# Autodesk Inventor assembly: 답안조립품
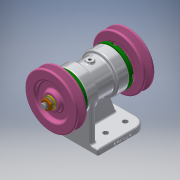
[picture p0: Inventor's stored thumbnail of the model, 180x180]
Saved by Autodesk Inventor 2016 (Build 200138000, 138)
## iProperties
Created: 2020-06
Part Number: 답안조립품
Material: 일반
Document SubType Name: Assembly
Designer: user
Author: user
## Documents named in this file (12)
- C:\Users\user\Desktop\700606V1056\답안조립품.iam
- C:\Users\user\Desktop\700606V1056\본체.ipt
- C:\Users\user\Desktop\700606V1056\베어링 6204.ipt
- C:\Users\user\Desktop\700606V1056\축.ipt
- C:\Users\user\Desktop\700606V1056\커버.ipt
- C:\Users\user\Desktop\700606V1056\오일 실 20 32 5.ipt
- C:\Users\user\Desktop\700606V1056\키 5x5x12.ipt
- C:\Users\user\Desktop\700606V1056\V-벨트풀리.ipt
- C:\Users\user\Desktop\700606V1056\평면 와셔 10x21.ipt
- C:\Users\user\Desktop\700606V1056\스프링 와셔 10.ipt
- C:\Users\user\Desktop\700606V1056\너트 M10.ipt
- C:\Users\user\Desktop\700606V1056\볼트 M4.ipt
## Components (2 placed, 1 different names)
1. V-벨트풀리:1 — 각도:5
2. V-벨트풀리:2 — 각도:6
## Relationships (2: Angle 2)
- 각도:5 [Angle]: V-벨트풀리:1
- 각도:6 [Angle]: V-벨트풀리:2
